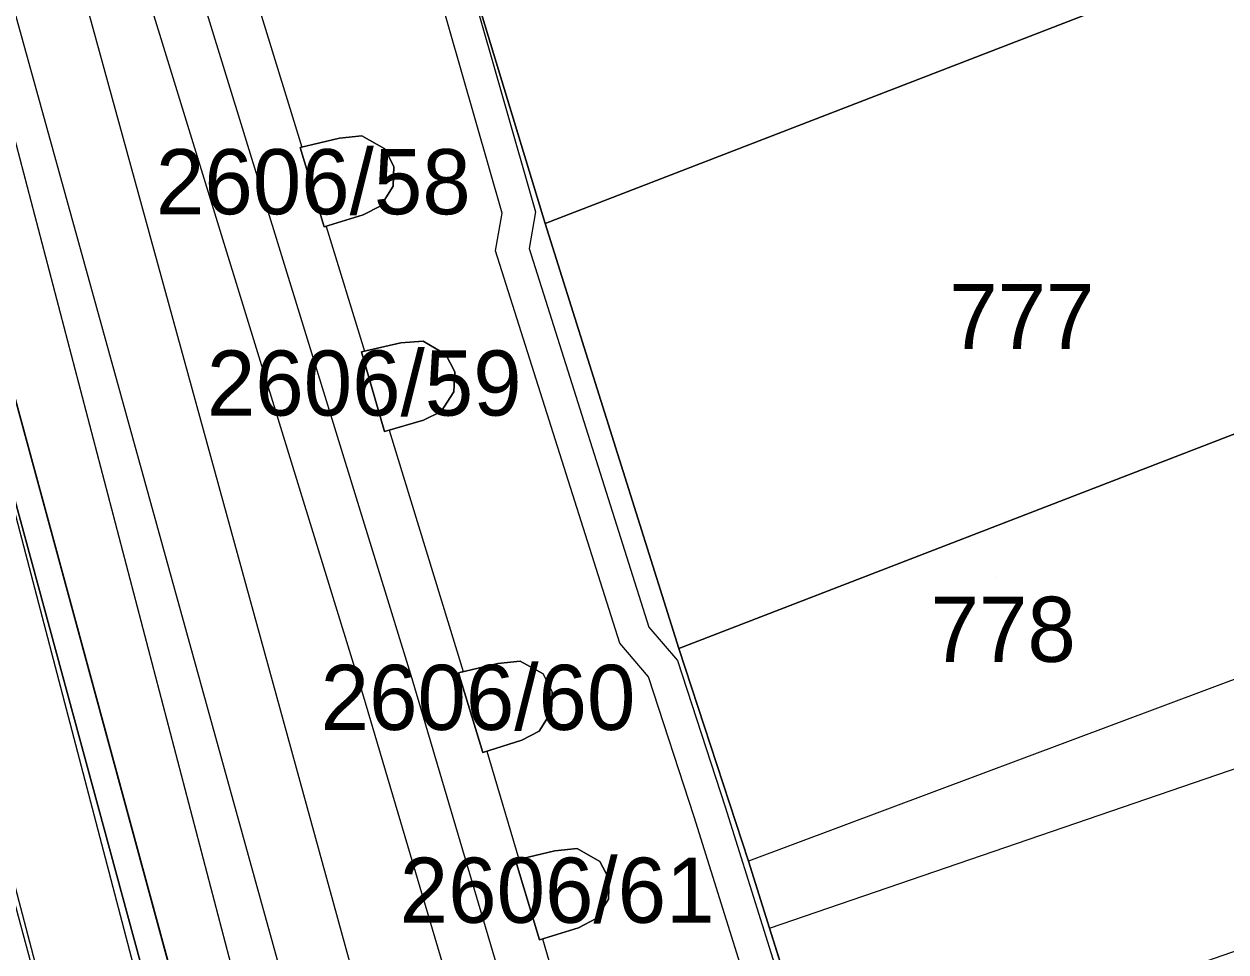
# Model space of a CAD drawing. Extents: x -263423 to -261326, y -1240067 to -1237864.
# Drawn here: x -262889.94 to -262853.02, y -1239226.89 to -1239198.41 of the extents above; entities that cross this region are included whole.
import ezdxf

# ---------------------------------------------------------------- set-up
doc = ezdxf.new("R2010")
doc.units = 0
for name, color, linetype in [('body_kn', 7, 'Continuous'), ('kladpar_druhypozemkov', 7, 'Continuous'), ('kladpar_hranice', 7, 'Continuous'), ('kladpar_parcelnecisla', 7, 'Continuous'), ('kladpar_plochy', 7, 'Continuous'), ('tarchy_linie', 7, 'Continuous'), ('zappar_hrandruhpozemk', 7, 'Continuous')]:
    doc.layers.add(name, color=color, linetype=linetype)

msp = doc.modelspace()

# ---------------------------------------------------------------- linework, layer by layer
at = {"layer": 'body_kn'}
for p, q in [((-262880.25, -1239201.91), (-262880.25, -1239201.91)), ((-262879.56, -1239201.84), (-262879.56, -1239201.84)), ((-262881.46, -1239202.2), (-262881.46, -1239202.2)), ((-262881.46, -1239202.2), (-262881.46, -1239202.2)), ((-262881.41, -1239202.19), (-262881.41, -1239202.19)), ((-262878.86, -1239202.24), (-262878.86, -1239202.24)), ((-262878.58, -1239202.78), (-262878.58, -1239202.78)), ((-262878.6, -1239203.39), (-262878.6, -1239203.39)), ((-262878.98, -1239203.99), (-262878.98, -1239203.99)), ((-262879.52, -1239204.27), (-262879.52, -1239204.27)), ((-262875.25, -1239204.22), (-262875.25, -1239204.22)), ((-262874.23, -1239204.17), (-262874.23, -1239204.17)), ((-262880.72, -1239204.64), (-262880.72, -1239204.64)), ((-262880.66, -1239204.62), (-262880.66, -1239204.62)), ((-262873.93, -1239204.53), (-262873.93, -1239204.53)), ((-262875.46, -1239205.37), (-262875.46, -1239205.37)), ((-262874.43, -1239205.3), (-262874.43, -1239205.3)), ((-262878.37, -1239208.2), (-262878.37, -1239208.2)), ((-262877.68, -1239208.14), (-262877.68, -1239208.14)), ((-262879.58, -1239208.47), (-262879.58, -1239208.47)), ((-262879.58, -1239208.47), (-262879.58, -1239208.47)), ((-262879.48, -1239208.45), (-262879.48, -1239208.45)), ((-262876.98, -1239208.55), (-262876.98, -1239208.55)), ((-262876.71, -1239209.09), (-262876.71, -1239209.09)), ((-262876.74, -1239209.7), (-262876.74, -1239209.7)), ((-262877.13, -1239210.3), (-262877.13, -1239210.3)), ((-262877.67, -1239210.57), (-262877.67, -1239210.57)), ((-262878.87, -1239210.92), (-262878.87, -1239210.92)), ((-262878.73, -1239210.88), (-262878.73, -1239210.88)), ((-262870.75, -1239216.92), (-262870.75, -1239216.92)), ((-262871.64, -1239217.42), (-262871.64, -1239217.42)), ((-262869.83, -1239217.58), (-262869.83, -1239217.58)), ((-262875.39, -1239218.04), (-262875.39, -1239218.04)), ((-262874.7, -1239217.97), (-262874.7, -1239217.97)), ((-262869.87, -1239217.95), (-262869.87, -1239217.95)), ((-262878.03, -1239218.5), (-262878.03, -1239218.5)), ((-262876.6, -1239218.33), (-262876.6, -1239218.33)), ((-262876.6, -1239218.33), (-262876.6, -1239218.33)), ((-262876.45, -1239218.29), (-262876.45, -1239218.29)), ((-262874, -1239218.36), (-262874, -1239218.36)), ((-262870.76, -1239218.45), (-262870.76, -1239218.45)), ((-262873.72, -1239218.91), (-262873.72, -1239218.91)), ((-262879.54, -1239218.96), (-262879.54, -1239218.96)), ((-262873.74, -1239219.51), (-262873.74, -1239219.51)), ((-262874.65, -1239220.39), (-262874.65, -1239220.39)), ((-262874.12, -1239220.12), (-262874.12, -1239220.12)), ((-262875.73, -1239220.73), (-262875.73, -1239220.73)), ((-262875.85, -1239220.77), (-262875.85, -1239220.77)), ((-262868.41, -1239222.44), (-262868.41, -1239222.44)), ((-262869.36, -1239222.75), (-262869.36, -1239222.75)), ((-262872.95, -1239223.72), (-262872.95, -1239223.72)), ((-262874.85, -1239224.08), (-262874.85, -1239224.08)), ((-262874.85, -1239224.08), (-262874.85, -1239224.08)), ((-262874.74, -1239224.05), (-262874.74, -1239224.05)), ((-262873.64, -1239223.79), (-262873.64, -1239223.79)), ((-262872.25, -1239224.12), (-262872.25, -1239224.12)), ((-262867.69, -1239224.11), (-262867.69, -1239224.11)), ((-262871.97, -1239224.66), (-262871.97, -1239224.66)), ((-262882.69, -1239225.25), (-262882.69, -1239225.25)), ((-262871.99, -1239225.27), (-262871.99, -1239225.27)), ((-262872.37, -1239225.87), (-262872.37, -1239225.87)), ((-262872.91, -1239226.15), (-262872.91, -1239226.15)), ((-262867.04, -1239226.16), (-262867.04, -1239226.16)), ((-262867.04, -1239226.16), (-262867.04, -1239226.16)), ((-262874.11, -1239226.52), (-262874.11, -1239226.52)), ((-262874.02, -1239226.49), (-262874.02, -1239226.49))]:
    msp.add_line(p, q, dxfattribs=at)
at = {"layer": 'kladpar_druhypozemkov'}
for p, q in [((-262880.16, -1239203.12), (-262880.16, -1239203.12)), ((-262859.37, -1239206.29), (-262859.37, -1239206.29)), ((-262878.29, -1239209.41), (-262878.29, -1239209.41)), ((-262860.07, -1239215.39), (-262860.07, -1239215.39)), ((-262875.37, -1239219.52), (-262875.37, -1239219.52)), ((-262874.03, -1239225.06), (-262874.03, -1239225.06))]:
    msp.add_line(p, q, dxfattribs=at)
at = {"layer": 'kladpar_hranice'}
for points in [[(-262855.82, -1239186.43), (-262828.81, -1239175.58), (-262826.63, -1239180.65), (-262826.21, -1239181.74), (-262821.8, -1239179.87), (-262820.83, -1239182.3), (-262846.85, -1239194.06), (-262873.93, -1239204.53), (-262876.94, -1239194.62), (-262875.22, -1239194.02), (-262855.82, -1239186.43)], [(-262820.83, -1239182.3), (-262818.54, -1239187.88), (-262812.59, -1239185.6), (-262812.35, -1239186.11), (-262809.89, -1239192.39), (-262812.26, -1239193.42), (-262814.12, -1239188.74), (-262815.91, -1239189.46), (-262813.93, -1239194.59), (-262819, -1239197.02), (-262836.55, -1239204.39), (-262843.66, -1239207.48), (-262869.83, -1239217.58), (-262873.93, -1239204.53), (-262846.85, -1239194.06), (-262820.83, -1239182.3)], [(-262843.66, -1239207.48), (-262836.55, -1239204.39), (-262819, -1239197.02), (-262813.93, -1239194.59), (-262815.91, -1239189.46), (-262814.12, -1239188.74), (-262812.26, -1239193.42), (-262809.89, -1239192.39), (-262808.16, -1239191.6), (-262808.04, -1239192.11), (-262804.3, -1239201.15), (-262802.43, -1239205.52), (-262811.78, -1239209.44), (-262838.39, -1239221.89), (-262865.44, -1239231.28), (-262867.04, -1239226.16), (-262867.69, -1239224.11), (-262869.83, -1239217.58), (-262843.66, -1239207.48)], [(-262876.94, -1239194.62), (-262873.93, -1239204.53), (-262869.83, -1239217.58), (-262867.69, -1239224.11), (-262867.04, -1239226.16), (-262865.44, -1239231.28), (-262860.88, -1239243.51), (-262859.93, -1239246.2), (-262853.69, -1239262.86), (-262850.58, -1239271.32), (-262845.56, -1239285.41), (-262844.17, -1239288.68), (-262843.15, -1239291.05), (-262840.62, -1239297.33)], [(-262893.54, -1239197.19), (-262892.9, -1239198.44), (-262892.79, -1239199.33), (-262892.76, -1239200.55), (-262875.18, -1239265.22), (-262874.5, -1239267.72), (-262870.89, -1239281.4), (-262870.34, -1239282.54), (-262869.36, -1239283.93), (-262868.26, -1239285.19), (-262869.45, -1239288.25), (-262872.13, -1239286.35), (-262871.76, -1239284.74), (-262871.59, -1239282.87), (-262871.66, -1239281.54), (-262875.31, -1239267.94), (-262876, -1239265.39), (-262893.6, -1239200.6), (-262893.66, -1239199.26), (-262893.7, -1239198.54), (-262894.26, -1239197.51)], [(-262894.26, -1239197.51), (-262893.7, -1239198.54), (-262893.66, -1239199.26), (-262893.6, -1239200.6), (-262876, -1239265.39), (-262875.31, -1239267.94), (-262871.66, -1239281.54), (-262871.59, -1239282.87), (-262871.76, -1239284.74), (-262872.13, -1239286.35), (-262869.45, -1239288.25), (-262868.26, -1239285.19), (-262869.36, -1239283.93), (-262870.34, -1239282.54), (-262870.89, -1239281.4), (-262874.5, -1239267.72), (-262875.18, -1239265.22), (-262892.76, -1239200.55), (-262892.79, -1239199.33), (-262892.9, -1239198.44), (-262893.54, -1239197.19)], [(-262881.46, -1239202.2), (-262880.25, -1239201.91), (-262879.56, -1239201.84), (-262878.86, -1239202.24), (-262878.58, -1239202.78), (-262878.6, -1239203.39), (-262878.98, -1239203.99), (-262879.52, -1239204.27), (-262880.72, -1239204.64), (-262881.46, -1239202.2)], [(-262880.25, -1239201.91), (-262881.46, -1239202.2), (-262880.72, -1239204.64), (-262879.52, -1239204.27), (-262878.98, -1239203.99), (-262878.6, -1239203.39), (-262878.58, -1239202.78), (-262878.86, -1239202.24), (-262879.56, -1239201.84), (-262880.25, -1239201.91)], [(-262879.58, -1239208.47), (-262878.37, -1239208.2), (-262877.68, -1239208.14), (-262876.98, -1239208.55), (-262876.71, -1239209.09), (-262876.74, -1239209.7), (-262877.13, -1239210.3), (-262877.67, -1239210.57), (-262878.87, -1239210.92), (-262879.58, -1239208.47)], [(-262878.37, -1239208.2), (-262879.58, -1239208.47), (-262878.87, -1239210.92), (-262877.67, -1239210.57), (-262877.13, -1239210.3), (-262876.74, -1239209.7), (-262876.71, -1239209.09), (-262876.98, -1239208.55), (-262877.68, -1239208.14), (-262878.37, -1239208.2)], [(-262876.6, -1239218.33), (-262875.39, -1239218.04), (-262874.7, -1239217.97), (-262874, -1239218.36), (-262873.72, -1239218.91), (-262873.74, -1239219.51), (-262874.12, -1239220.12), (-262874.65, -1239220.39), (-262875.85, -1239220.77), (-262876.6, -1239218.33)], [(-262875.39, -1239218.04), (-262876.6, -1239218.33), (-262875.85, -1239220.77), (-262874.65, -1239220.39), (-262874.12, -1239220.12), (-262873.74, -1239219.51), (-262873.72, -1239218.91), (-262874, -1239218.36), (-262874.7, -1239217.97), (-262875.39, -1239218.04)], [(-262874.85, -1239224.08), (-262873.64, -1239223.79), (-262872.95, -1239223.72), (-262872.25, -1239224.12), (-262871.97, -1239224.66), (-262871.99, -1239225.27), (-262872.37, -1239225.87), (-262872.91, -1239226.15), (-262874.11, -1239226.52), (-262874.85, -1239224.08)], [(-262873.64, -1239223.79), (-262874.85, -1239224.08), (-262874.11, -1239226.52), (-262872.91, -1239226.15), (-262872.37, -1239225.87), (-262871.99, -1239225.27), (-262871.97, -1239224.66), (-262872.25, -1239224.12), (-262872.95, -1239223.72), (-262873.64, -1239223.79)]]:
    msp.add_lwpolyline(points, dxfattribs=at)
at = {"layer": 'kladpar_plochy'}
for p, q in [((-262876.94, -1239194.62), (-262873.93, -1239204.53)), ((-262893.6, -1239200.6), (-262876, -1239265.39)), ((-262875.18, -1239265.22), (-262892.76, -1239200.55)), ((-262880.25, -1239201.91), (-262881.46, -1239202.2)), ((-262879.56, -1239201.84), (-262880.25, -1239201.91)), ((-262878.86, -1239202.24), (-262879.56, -1239201.84)), ((-262881.46, -1239202.2), (-262880.72, -1239204.64)), ((-262878.58, -1239202.78), (-262878.86, -1239202.24)), ((-262878.6, -1239203.39), (-262878.58, -1239202.78)), ((-262878.98, -1239203.99), (-262878.6, -1239203.39)), ((-262879.52, -1239204.27), (-262878.98, -1239203.99)), ((-262880.72, -1239204.64), (-262879.52, -1239204.27)), ((-262873.93, -1239204.53), (-262869.83, -1239217.58)), ((-262878.37, -1239208.2), (-262879.58, -1239208.47)), ((-262877.68, -1239208.14), (-262878.37, -1239208.2)), ((-262876.98, -1239208.55), (-262877.68, -1239208.14)), ((-262879.58, -1239208.47), (-262878.87, -1239210.92)), ((-262876.71, -1239209.09), (-262876.98, -1239208.55)), ((-262876.74, -1239209.7), (-262876.71, -1239209.09)), ((-262877.13, -1239210.3), (-262876.74, -1239209.7)), ((-262877.67, -1239210.57), (-262877.13, -1239210.3)), ((-262878.87, -1239210.92), (-262877.67, -1239210.57)), ((-262869.83, -1239217.58), (-262867.69, -1239224.11)), ((-262875.39, -1239218.04), (-262876.6, -1239218.33)), ((-262874.7, -1239217.97), (-262875.39, -1239218.04)), ((-262874, -1239218.36), (-262874.7, -1239217.97)), ((-262876.6, -1239218.33), (-262875.85, -1239220.77)), ((-262873.72, -1239218.91), (-262874, -1239218.36)), ((-262873.74, -1239219.51), (-262873.72, -1239218.91)), ((-262874.12, -1239220.12), (-262873.74, -1239219.51)), ((-262875.85, -1239220.77), (-262874.65, -1239220.39)), ((-262874.65, -1239220.39), (-262874.12, -1239220.12)), ((-262872.95, -1239223.72), (-262873.64, -1239223.79)), ((-262872.25, -1239224.12), (-262872.95, -1239223.72)), ((-262873.64, -1239223.79), (-262874.85, -1239224.08)), ((-262874.85, -1239224.08), (-262874.11, -1239226.52)), ((-262871.97, -1239224.66), (-262872.25, -1239224.12)), ((-262867.69, -1239224.11), (-262867.04, -1239226.16)), ((-262871.99, -1239225.27), (-262871.97, -1239224.66)), ((-262872.37, -1239225.87), (-262871.99, -1239225.27)), ((-262872.91, -1239226.15), (-262872.37, -1239225.87)), ((-262874.11, -1239226.52), (-262872.91, -1239226.15)), ((-262867.04, -1239226.16), (-262865.44, -1239231.28))]:
    msp.add_line(p, q, dxfattribs=at)
for points in [[(-262855.82, -1239186.43), (-262828.81, -1239175.58), (-262826.63, -1239180.65), (-262826.21, -1239181.74), (-262821.8, -1239179.87), (-262820.83, -1239182.3), (-262846.85, -1239194.06), (-262873.93, -1239204.53), (-262876.94, -1239194.62), (-262875.22, -1239194.02)], [(-262820.83, -1239182.3), (-262818.54, -1239187.88), (-262812.59, -1239185.6), (-262812.35, -1239186.11), (-262809.89, -1239192.39), (-262812.26, -1239193.42), (-262814.12, -1239188.74), (-262815.91, -1239189.46), (-262813.93, -1239194.59), (-262819, -1239197.02), (-262836.55, -1239204.39), (-262843.66, -1239207.48), (-262869.83, -1239217.58), (-262873.93, -1239204.53), (-262846.85, -1239194.06)], [(-262843.66, -1239207.48), (-262836.55, -1239204.39), (-262819, -1239197.02), (-262813.93, -1239194.59), (-262815.91, -1239189.46), (-262814.12, -1239188.74), (-262812.26, -1239193.42), (-262809.89, -1239192.39), (-262808.16, -1239191.6), (-262808.04, -1239192.11), (-262804.3, -1239201.15), (-262802.43, -1239205.52), (-262811.78, -1239209.44), (-262838.39, -1239221.89), (-262865.44, -1239231.28), (-262867.04, -1239226.16), (-262867.69, -1239224.11), (-262869.83, -1239217.58)], [(-262881.46, -1239202.2), (-262880.25, -1239201.91), (-262879.56, -1239201.84), (-262878.86, -1239202.24), (-262878.58, -1239202.78), (-262878.6, -1239203.39), (-262878.98, -1239203.99), (-262879.52, -1239204.27), (-262880.72, -1239204.64)], [(-262879.58, -1239208.47), (-262878.37, -1239208.2), (-262877.68, -1239208.14), (-262876.98, -1239208.55), (-262876.71, -1239209.09), (-262876.74, -1239209.7), (-262877.13, -1239210.3), (-262877.67, -1239210.57), (-262878.87, -1239210.92)], [(-262876.6, -1239218.33), (-262875.39, -1239218.04), (-262874.7, -1239217.97), (-262874, -1239218.36), (-262873.72, -1239218.91), (-262873.74, -1239219.51), (-262874.12, -1239220.12), (-262874.65, -1239220.39), (-262875.85, -1239220.77)], [(-262874.85, -1239224.08), (-262873.64, -1239223.79), (-262872.95, -1239223.72), (-262872.25, -1239224.12), (-262871.97, -1239224.66), (-262871.99, -1239225.27), (-262872.37, -1239225.87), (-262872.91, -1239226.15), (-262874.11, -1239226.52)]]:
    msp.add_lwpolyline(points, close=True, dxfattribs=at)
msp.add_lwpolyline([(-262893.54, -1239197.19), (-262892.9, -1239198.44), (-262892.79, -1239199.33), (-262892.76, -1239200.55), (-262875.18, -1239265.22), (-262874.5, -1239267.72), (-262870.89, -1239281.4), (-262870.34, -1239282.54), (-262869.36, -1239283.93), (-262868.26, -1239285.19), (-262869.45, -1239288.25), (-262872.13, -1239286.35), (-262871.76, -1239284.74), (-262871.59, -1239282.87), (-262871.66, -1239281.54), (-262875.31, -1239267.94), (-262876, -1239265.39), (-262893.6, -1239200.6), (-262893.66, -1239199.26), (-262893.7, -1239198.54), (-262894.26, -1239197.51)], dxfattribs=at)
at = {"layer": 'tarchy_linie'}
for points in [[(-263002.97, -1238844.59), (-262980.25, -1238906.63), (-262945.58, -1239009.09), (-262938.29, -1239035.86), (-262916.38, -1239115.82), (-262894.12, -1239198.57), (-262876.1, -1239267.26), (-262891.06, -1239270.91), (-262884.2, -1239310.37), (-262877, -1239350.49), (-262869.73, -1239390.34), (-262861.27, -1239427.46), (-262857.92, -1239442.13), (-262856.51, -1239448.31), (-262843.28, -1239506.14), (-262818.17, -1239595.69)], [(-262939.39, -1239021.15), (-262934.2, -1239037.72), (-262927.16, -1239063.69), (-262920.98, -1239083.65), (-262911.91, -1239113.75), (-262904.59, -1239137.31), (-262894.43, -1239170.66), (-262879.54, -1239218.96), (-262874.31, -1239236.62), (-262867.48, -1239260.06), (-262865.11, -1239267.42), (-262873.73, -1239264.88), (-262891.31, -1239197.83), (-262913.63, -1239115.08), (-262935.59, -1239035.12), (-262939.39, -1239021.15)], [(-262931.57, -1239078.69), (-262927.11, -1239096.92), (-262921.96, -1239117.89), (-262918.29, -1239132.37), (-262910.23, -1239164.23), (-262903.15, -1239192.92), (-262896.96, -1239218.17), (-262893.46, -1239232.55), (-262888.28, -1239253.85), (-262887.41, -1239260.33), (-262887.33, -1239268.2), (-262879.36, -1239266.25), (-262896.93, -1239199.31), (-262919.13, -1239116.56), (-262940.99, -1239036.6)], [(-262919.47, -1239083.19), (-262910.4, -1239113.29), (-262903.08, -1239136.85), (-262892.92, -1239170.2), (-262878.03, -1239218.5), (-262872.8, -1239236.18), (-262865.97, -1239259.6), (-262862.37, -1239270.8), (-262860.78, -1239275.15), (-262855.16, -1239281.3), (-262847.42, -1239296.93), (-262841.21, -1239314.37), (-262837.3, -1239325.72), (-262833.82, -1239334.62), (-262823.57, -1239363.35), (-262812.24, -1239393.87)], [(-262891.41, -1239169.74), (-262881.41, -1239202.19), (-262881.46, -1239202.2), (-262880.72, -1239204.64), (-262880.66, -1239204.62), (-262879.48, -1239208.45), (-262879.58, -1239208.47), (-262878.87, -1239210.92), (-262878.73, -1239210.88), (-262876.45, -1239218.29), (-262876.6, -1239218.33), (-262875.85, -1239220.77), (-262875.73, -1239220.73), (-262874.74, -1239224.05), (-262874.85, -1239224.08), (-262874.11, -1239226.52), (-262874.02, -1239226.49), (-262872.92, -1239230.24)], [(-262890.7, -1239253.23), (-262886.94, -1239252.51), (-262885.14, -1239251.96), (-262883.22, -1239251.37), (-262881.59, -1239250.87), (-262880.08, -1239250.37), (-262879.29, -1239250.11), (-262876.32, -1239249.13), (-262874.29, -1239248.46), (-262870.3, -1239247.13), (-262868.21, -1239246.21), (-262862.28, -1239244.82), (-262864.61, -1239236.92), (-262867.84, -1239227.59), (-262869.36, -1239222.75), (-262870.76, -1239218.45), (-262871.64, -1239217.42), (-262875.46, -1239205.37), (-262875.25, -1239204.22), (-262878.13, -1239194.18)], [(-262877.17, -1239193.9), (-262874.23, -1239204.17), (-262874.43, -1239205.3), (-262870.75, -1239216.92), (-262869.87, -1239217.95), (-262868.41, -1239222.44), (-262866.89, -1239227.27), (-262863.66, -1239236.62), (-262861.02, -1239245.55), (-262867.89, -1239247.16), (-262869.94, -1239248.07), (-262874.05, -1239249.43), (-262876.06, -1239250.1), (-262879.02, -1239251.08), (-262879.82, -1239251.34), (-262881.29, -1239251.83), (-262882.96, -1239252.34), (-262884.86, -1239252.92), (-262886.65, -1239253.45)], [(-262876.94, -1239194.62), (-262873.93, -1239204.53), (-262869.83, -1239217.58), (-262867.69, -1239224.11), (-262867.04, -1239226.16), (-262865.44, -1239231.28), (-262860.88, -1239243.51), (-262859.93, -1239246.2), (-262859.89, -1239246.31), (-262867.57, -1239248.11), (-262869.58, -1239249)]]:
    msp.add_lwpolyline(points, dxfattribs=at)
at = {"layer": 'zappar_hrandruhpozemk'}
for p, q in [((-262841.2, -1239214.2), (-262867.69, -1239224.11)), ((-262867.04, -1239226.16), (-262840.19, -1239216.96))]:
    msp.add_line(p, q, dxfattribs=at)
for points in [[(-262937.97, -1239016.31), (-262934.66, -1239027.99), (-262902.52, -1239144.64), (-262891.29, -1239186.07), (-262888.2, -1239197.19), (-262878.19, -1239233.56), (-262876.42, -1239236.1)], [(-262893.25, -1239186.79), (-262890.34, -1239197.61), (-262882.69, -1239225.25), (-262880.02, -1239234.88)], [(-262899.73, -1239190.15), (-262889.66, -1239227.51), (-262887.35, -1239236.1)]]:
    msp.add_lwpolyline(points, dxfattribs=at)

# ---------------------------------------------------------------- texts
at = {"layer": 'kladpar_parcelnecisla'}
for s, p in [('2606/58', (-262885.888, -1239204.25)), ('777', (-262861.527, -1239208.39)), ('2606/59', (-262884.324, -1239210.43)), ('778', (-262862.098, -1239217.99)), ('2606/60', (-262880.83, -1239220.08)), ('2606/61', (-262878.4, -1239226))]:
    msp.add_text(s, height=2, dxfattribs=at).set_placement(p)

doc.saveas('drawing.dxf')
